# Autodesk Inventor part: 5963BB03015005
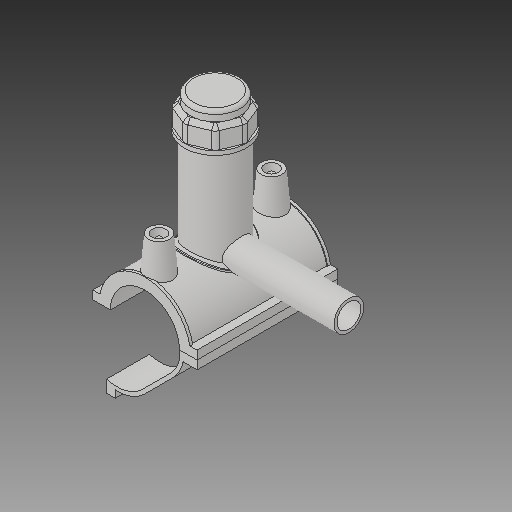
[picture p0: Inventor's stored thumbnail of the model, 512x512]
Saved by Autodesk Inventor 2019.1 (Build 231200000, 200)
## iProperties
Created: 2017-07
Part Number: 5963BB03015005
Material: Generic
Description: PLASSON TAPPING SADDLE 1 1/2''IPS x 1 1/2''IPS
Document SubType Name: Modeling
Designer: KIM
Mass: 1712.7 g
Surface Area: 2671.49 cm^2
Volume: 1712.7 cm^3
Density: 1 g/cm^3
Appearance: Default
Author: KIM
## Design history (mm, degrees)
derived "5963B.ipt"
feature "Solid1::5963B.ipt"
feature "Solid2::5963B.ipt"
feature "Solid4::5963B.ipt"
feature "Solid5::5963B.ipt"
tag "TaggingFeature1"
body "Solid1"
body "Solid2"
other parameters: "d_" = 49.1, "B_" = 74.168, "L_" = 100.076, "d_t" = 6, "H_2" = 98.044, "H_1" = 6.858, "d_1" = 21.2, "H_" = 94.996, "d1" = 63.83, "d148" = 0.7365, "d160" = 0.7365, "d169" = 3.2805, "d192" = 6.1236, "d0" = 49.1, "d2" = 74.168, "d3" = 12.275, "d4" = 100.076, "d5" = 0, "d6" = 0.1, "d8" = 0, "d19" = 6, "d20" = 6, "d21" = 60.0456, "d23" = 0, "d24" = 30.0228, "d26" = 0, "d29" = 3, "d30" = 16.36667, "d31" = 6, "d32" = 0, "d33" = 0, "d34" = 0.6, "d40" = 33.1916, "d41" = 44.19, "d43" = 0, "d45" = 0, "d47" = 91.9606, "d70" = 15, "d72" = 0, "d73" = 6, "d75" = 5, "d76" = 0, "d77" = 2.455, "d78" = 54.55, "d79" = 15, "d80" = 40.0304, "d82" = 5 deg, "d84" = 4, "d85" = 14, "d86" = 0, "d87" = 3, "d88" = 0, "d89" = 1, "d90" = 1, "d91" = 80.0608, "d92" = 0, "d93" = 0.5, "d94" = 25.84211, "d96" = 65.1066, "d97" = 2.00152, "d98" = 0, "d102" = 0.491, "d120" = 140 deg, "d121" = 24.228, "d122" = 20 deg, "d123" = 127.66, "d124" = 38.298, "d126" = 0, "d143" = 50.573, "d145" = 11.33077, "d149" = 0.7365, "d150" = 12.46385, "d153" = 100.076, "d154" = 0, "d156" = 31.915, "d157" = 160 deg, "d159" = 2.946, "d161" = 0.7365, "d162" = 60.0456, "d163" = 0, "d164" = 24.55, "d167" = 4.91, "d168" = 31.13659, "d170" = 3.2805, "d172" = 0, "d173" = 1, "d175" = 24.55, "d176" = 20 deg, "d177" = 3.437, "d178" = 14.73, "d180" = 0, "d183" = 5.892, "d184" = 2.7496, "d185" = 32.5247, "d186" = 32.5247, "d187" = 31.915, "d188" = 4.419, "d189" = 3.437, "d190" = 0, "d191" = 47.8725, "d193" = 6.1236, "d194" = 3.50266, "d195" = 90 deg, "d197" = 0, "d199" = 0, "d200" = 7.365, "d202" = 0, "d203" = 98.044, "d204" = 41.9805, "d205" = 30.933, "d206" = 37.5615, "d207" = 73.533, "d208" = 76.47432, "d209" = 91.18092, "d210" = 38.0034, "d211" = 44.19, "d212" = 35.352, "d213" = -3.3678, "d216" = 0, "d217" = 4.91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
